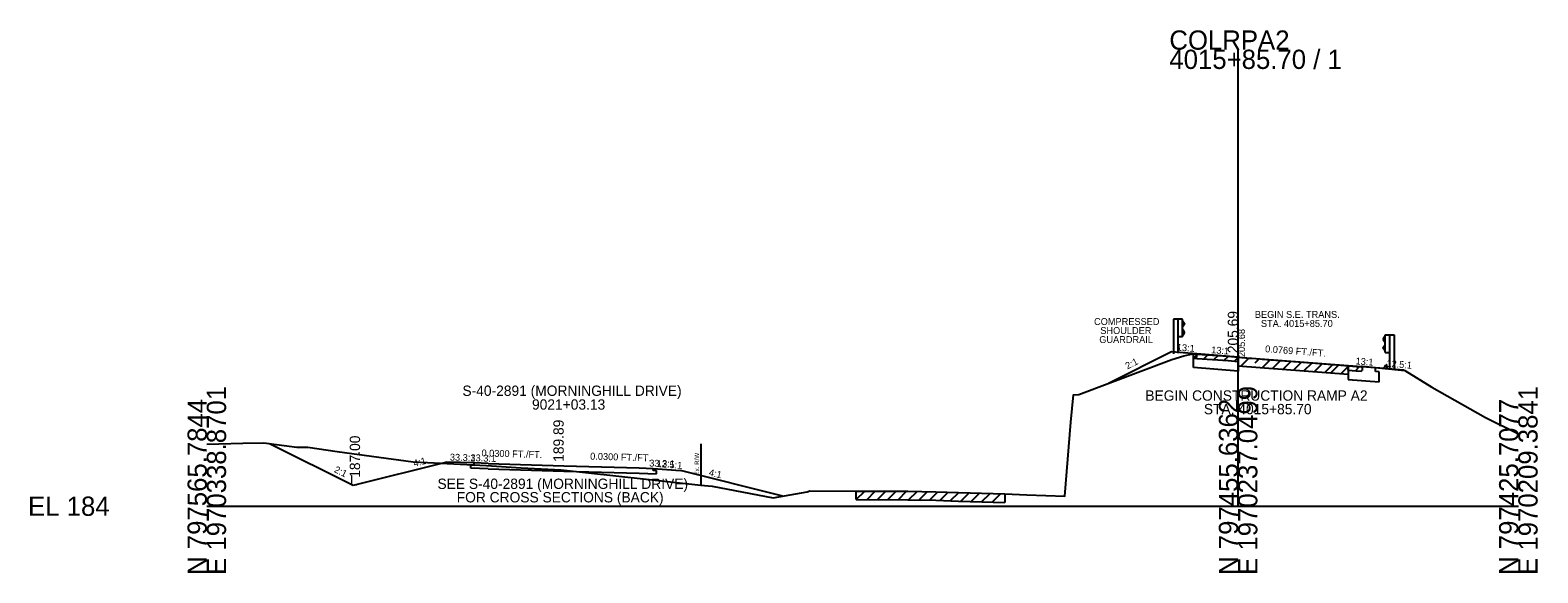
# Model space of a CAD drawing. Extents: x -26 to 1971083, y -10 to 798159.
# Drawn here: x -25.7 to 193.6, y -9.7 to 69.2 of the extents above; entities that cross this region are included whole.
import ezdxf

# ---------------------------------------------------------------- set-up
doc = ezdxf.new("R2010")
doc.units = 0
for name, color, linetype in [('RD_GPK_XS_Cell', 7, 'Continuous'), ('RD_XS_Base', 7, 'Continuous'), ('RD_XS_CurbTop', 7, 'Continuous'), ('RD_XS_EarthShd', 7, 'Continuous'), ('RD_XS_ExGround', 7, 'Continuous'), ('RD_XS_ExPaveRet', 7, 'Continuous'), ('RD_XS_ExRW', 7, 'Continuous'), ('RD_XS_GR', 7, 'Continuous'), ('RD_XS_Misc_Line', 7, 'Continuous'), ('RD_XS_Pave', 7, 'Continuous'), ('RD_XS_PaveOvlay', 7, 'Continuous'), ('RD_XS_PaveShd', 7, 'Continuous'), ('RD_XS_TieSlope', 7, 'Continuous'), ('RD_XS_TX_Elev_EX', 7, 'Continuous'), ('RD_XS_TX_Elev_PR', 7, 'Continuous'), ('RD_XS_TX_Misc', 7, 'Continuous'), ('RD_XS_TX_MkPT', 7, 'Continuous'), ('RD_XS_TX_Notes', 7, 'Continuous'), ('RD_XS_TX_Profile', 7, 'Continuous'), ('RD_XS_TX_ShdSlope', 7, 'Continuous'), ('RD_XS_TX_Slope', 7, 'Continuous'), ('RD_XS_TX_Station', 7, 'Continuous')]:
    doc.layers.add(name, color=color, linetype=linetype)

msp = doc.modelspace()

# ---------------------------------------------------------------- linework, layer by layer
at = {"layer": 'RD_GPK_XS_Cell'}
for p, q in [((150, 0), (150, 66.38)), ((0, 0), (150, 0)), ((150, 0), (190.76, 0))]:
    msp.add_line(p, q, dxfattribs=at)
at = {"layer": 'RD_XS_Base'}
for p, q in [((144, 21.6), (144, 22.16)), ((143.5, 21.63), (144, 21.6)), ((143.5, 20.15), (143.5, 21.63)), ((150, 19.65), (143.5, 20.15)), ((170, 19.6), (170, 20.16)), ((166, 18.42), (170.5, 18.08)), ((170.5, 19.56), (170, 19.6)), ((170.5, 18.08), (170.5, 19.56)), ((38.41, 5.99), (38.91, 5.98)), ((38.41, 5.51), (38.41, 5.99)), ((40.91, 5.44), (38.41, 5.51)), ((38.91, 5.98), (38.91, 6.28)), ((40.91, 5.44), (51.91, 5.11)), ((51.91, 5.11), (62.91, 4.78)), ((62.91, 4.78), (65.41, 4.7)), ((64.91, 5.2), (64.91, 5.5)), ((65.41, 5.18), (64.91, 5.2)), ((65.41, 4.7), (65.41, 5.18))]:
    msp.add_line(p, q, dxfattribs=at)
at = {"layer": 'RD_XS_CurbTop'}
for p, q in [((171.23, 20.06), (171.47, 20.51)), ((171.23, 20.06), (171.69, 20.02)), ((171.69, 20.02), (171.63, 20.46))]:
    msp.add_line(p, q, dxfattribs=at)
msp.add_ellipse((171.55, 20.43), major_axis=(0, -0.131), ratio=0.686, start_param=1.762783, end_param=4.036677, dxfattribs=at)
at = {"layer": 'RD_XS_EarthShd'}
for p, q in [((144, 22.16), (142.06, 22.31)), ((170, 20.16), (171.23, 20.06)), ((38.91, 6.28), (34.91, 6.4)), ((64.91, 5.5), (68.92, 5.18))]:
    msp.add_line(p, q, dxfattribs=at)
at = {"layer": 'RD_XS_ExGround'}
msp.add_lwpolyline([(0, 9.01), (5.25, 9.16), (8.3, 9.2), (13.11, 8.59), (14.69, 8.56), (18.98, 7.95), (30.02, 6.45), (32.11, 6.34), (40.68, 5.92), (45.71, 5.6), (51.53, 5.28), (71.86, 3.08), (72.94, 2.98), (73.48, 2.91), (82.4, 1.2), (87.3, 2.11), (87.7, 2.22), (94.46, 2.2), (101.96, 2.16), (106.04, 2.11), (109.32, 2), (116.09, 1.79), (119.29, 1.66), (124.78, 1.45), (125.69, 12.23), (126.08, 16.21), (126.84, 16.25), (140.37, 21.31), (142.12, 21.88), (143, 22.04), (143.49, 22.13), (144, 22.09), (148.57, 21.81), (150, 21.68), (151.62, 21.52), (152, 21.5), (164.93, 20.53), (167.17, 20.3), (167.9, 20.25), (168.05, 20.37), (174.23, 19.75), (178.16, 17.29), (185.99, 12.92), (190.76, 10.54)], dxfattribs=at)
at = {"layer": 'RD_XS_ExPaveRet'}
for p, q in [((143.49, 21.5), (143.49, 22.13)), ((143.49, 21.5), (144, 21.46)), ((144, 21.46), (148.57, 21.19)), ((148.57, 21.19), (150, 21.05)), ((150, 20.4), (150, 21.68)), ((150, 21.68), (150, 21.05)), ((150, 20.4), (166, 19.2)), ((166, 20.42), (166, 19.17)), ((166, 19.8), (166, 20.42)), ((166, 19.8), (167.17, 19.68)), ((167.9, 19.62), (168.05, 19.75)), ((168.05, 20.37), (168.05, 19.75)), ((167.17, 19.68), (167.9, 19.62)), ((94.46, 0.95), (94.46, 2.2)), ((94.46, 0.95), (101.96, 0.91)), ((101.96, 0.91), (106.04, 0.86)), ((106.04, 0.86), (109.32, 0.75)), ((109.32, 0.75), (116.09, 0.54)), ((116.09, 1.79), (116.09, 0.54))]:
    msp.add_line(p, q, dxfattribs=at)
at = {"layer": 'RD_XS_ExRW'}
msp.add_line((71.86, 9.08), (71.86, 3.08), dxfattribs=at)
at = {"layer": 'RD_XS_GR'}
for p, q in [((141.24, 27.18), (140.58, 27.18)), ((140.58, 27.18), (140.58, 22.13)), ((141.91, 27.18), (141.24, 27.18)), ((141.24, 27.18), (141.24, 22.24)), ((141.91, 24.61), (141.91, 27.18)), ((141.91, 27.02), (142.18, 26.58)), ((142.18, 26.47), (141.91, 26.03)), ((142.18, 26.58), (142.18, 26.47)), ((141.91, 24.61), (141.24, 24.61)), ((142.18, 25.32), (141.91, 25.76)), ((141.91, 24.77), (142.18, 25.21)), ((142.18, 25.21), (142.18, 25.32)), ((171.37, 24.77), (171.1, 24.33)), ((171.1, 24.33), (171.1, 24.22)), ((171.1, 24.22), (171.37, 23.78)), ((171.37, 24.93), (172.04, 24.93)), ((171.37, 22.37), (171.37, 24.93)), ((172.04, 24.93), (172.7, 24.93)), ((172.04, 24.93), (172.04, 19.99)), ((172.7, 24.93), (172.7, 19.88)), ((171.1, 23.08), (171.37, 23.52)), ((171.1, 22.97), (171.1, 23.08)), ((171.37, 22.53), (171.1, 22.97)), ((171.37, 22.37), (172.04, 22.37))]:
    msp.add_line(p, q, dxfattribs=at)
at = {"layer": 'RD_XS_Misc_Line'}
for p, q in [((143.49, 21.5), (144.07, 22.09)), ((144.99, 21.4), (145.58, 21.99)), ((146.49, 21.31), (147.08, 21.9)), ((147.99, 21.22), (148.58, 21.81)), ((149.49, 21.1), (150.06, 21.67)), ((150.4, 20.37), (151.56, 21.53)), ((152.49, 20.83), (153.07, 21.42)), ((153.49, 20.13), (154.67, 21.3)), ((155.01, 20.02), (156.19, 21.18)), ((156.53, 19.91), (157.71, 21.07)), ((158.05, 19.79), (159.23, 20.95)), ((159.57, 19.68), (160.75, 20.84)), ((161.09, 19.57), (162.27, 20.73)), ((162.61, 19.45), (163.79, 20.61)), ((163.47, 19.39), (164.64, 20.55)), ((164.99, 19.27), (166.12, 20.41)), ((167.06, 19.69), (167.63, 20.27)), ((94.46, 0.95), (95.71, 2.19)), ((95.98, 0.94), (97.23, 2.18)), ((97.5, 0.93), (98.75, 2.17)), ((99.02, 0.92), (100.27, 2.17)), ((100.54, 0.91), (101.79, 2.16)), ((102.06, 0.9), (103.31, 2.14)), ((103.58, 0.89), (104.83, 2.13)), ((105.1, 0.87), (106.34, 2.1)), ((106.62, 0.84), (107.84, 2.05)), ((108.14, 0.79), (109.36, 2)), ((109.66, 0.74), (110.88, 1.95)), ((111.18, 0.69), (112.4, 1.9)), ((112.7, 0.64), (113.92, 1.86)), ((114.22, 0.6), (115.44, 1.81))]:
    msp.add_line(p, q, dxfattribs=at)
at = {"layer": 'RD_XS_Pave'}
for p, q in [((150, 21.69), (166, 20.46)), ((40.91, 6.22), (51.91, 5.89)), ((51.91, 5.89), (62.91, 5.56))]:
    msp.add_line(p, q, dxfattribs=at)
at = {"layer": 'RD_XS_PaveOvlay'}
for p, q in [((150, 21.68), (150, 19.65)), ((150, 20.63), (150, 19.68)), ((153.49, 21.38), (164.05, 20.59)), ((164.05, 20.59), (166, 20.42)), ((166, 20.42), (166, 18.42))]:
    msp.add_line(p, q, dxfattribs=at)
at = {"layer": 'RD_XS_PaveShd'}
for p, q in [((150, 21.69), (144, 22.16)), ((166, 20.46), (170, 20.16)), ((40.91, 6.22), (38.91, 6.28)), ((62.91, 5.56), (64.91, 5.5))]:
    msp.add_line(p, q, dxfattribs=at)
at = {"layer": 'RD_XS_TieSlope'}
for p, q in [((140.31, 22.44), (131.14, 17.86)), ((142.06, 22.31), (140.31, 22.44)), ((171.23, 20.06), (174.06, 19.83)), ((174.06, 19.83), (174.23, 19.75)), ((21.31, 3), (9.13, 9.09)), ((34.91, 6.4), (21.31, 3)), ((83.8, 1.46), (68.92, 5.18))]:
    msp.add_line(p, q, dxfattribs=at)

# ---------------------------------------------------------------- texts
at = {"layer": 'RD_GPK_XS_Cell'}
for s, p in [('COLRPA2', (140, 66.38)), ('4015+85.70 / 1', (140, 63.58)), ('EL 184', (-26, -1.4))]:
    msp.add_text(s, height=2.8, dxfattribs=at).set_placement(p)
for s, p in [('N 797565.7844', (0, -10)), ('E 1970338.8701', (2.8, -10)), ('N 797455.6362', (150, -10)), ('E 1970237.0499', (152.8, -10)), ('N 797425.7077', (190.76, -10)), ('E 1970209.3841', (193.56, -10))]:
    msp.add_text(s, height=2.8, rotation=90, dxfattribs=at).set_placement(p)
at = {"layer": 'RD_XS_ExRW'}
msp.add_text('Ex. R/W ', height=0.65, rotation=90, dxfattribs=at).set_placement((71.61, 4.47))
at = {"layer": 'RD_XS_TX_Elev_EX'}
msp.add_text('205.68', height=1, rotation=90, dxfattribs=at).set_placement((151, 21.68))
at = {"layer": 'RD_XS_TX_Elev_PR'}
for s, p in [(' 205.69', (150, 21.69)), (' 189.89', (51.91, 5.89))]:
    msp.add_text(s, height=1.5, rotation=90, dxfattribs=at).set_placement(p)
at = {"layer": 'RD_XS_TX_Misc'}
msp.add_text('187.00', height=1.5, rotation=90, dxfattribs=at).set_placement((22.29, 4.13))
at = {"layer": 'RD_XS_TX_MkPT'}
msp.add_text('L', height=1.5, dxfattribs=at).set_placement((20.81, 3))
at = {"layer": 'RD_XS_TX_Notes'}
for s, p in [('COMPRESSED', (129.05, 26.35)), ('BEGIN S.E. TRANS.', (152.44, 27.38)), ('STA. 4015+85.70', (153.32, 26.07)), ('GUARDRAIL', (129.81, 23.73)), ('SHOULDER', (129.96, 25.04))]:
    msp.add_text(s, height=1, rotation=360, dxfattribs=at).set_placement(p)
for s, p in [('BEGIN CONSTRUCTION RAMP A2', (136.51, 15.34)), ('STA. 4015+85.70', (145.02, 13.37)), ('SEE S-40-2891 (MORNINGHILL DRIVE)', (33.55, 2.51)), ('FOR CROSS SECTIONS (BACK)', (36.35, 0.55))]:
    msp.add_text(s, height=1.5, dxfattribs=at).set_placement(p)
at = {"layer": 'RD_XS_TX_Profile'}
for p in [(38.34, 6.55), (64.34, 5.77)]:
    msp.add_text('33.3:1', height=1, rotation=358.2815, dxfattribs=at).set_placement(p)
at = {"layer": 'RD_XS_TX_ShdSlope'}
for s, rotation, p in [('13:1', 355.6026, (141.06, 22.63)), ('12.5:1', 355.4261, (171.54, 20.28)), ('33.3:1', 358.2815, (35.34, 6.64)), ('12.5:1', 355.4323, (65.41, 5.71))]:
    msp.add_text(s, height=1, rotation=rotation, dxfattribs=at).set_placement(p)
at = {"layer": 'RD_XS_TX_Slope'}
for s, rotation, p in [('13:1', 355.6026, (146.06, 22.25)), ('0.0769 FT./FT.', 355.6026, (153.9, 22.4)), ('2:1', 26.5651, (133.9, 19.87)), ('13:1', 355.6026, (167.06, 20.63)), ('4:1', 14.0362, (30.17, 5.73)), ('0.0300 FT./FT.', 358.2815, (39.94, 7.25)), ('0.0300 FT./FT.', 358.2815, (55.75, 6.78)), ('2:1', 333.435, (18.43, 5)), ('4:1', 346.9381, (72.96, 4.46))]:
    msp.add_text(s, height=1, rotation=rotation, dxfattribs=at).set_placement(p)
at = {"layer": 'RD_XS_TX_Station'}
for s, p in [('S-40-2891 (MORNINGHILL DRIVE)', (37.18, 16.04)), ('9021+03.13', (47.3, 14.04))]:
    msp.add_text(s, height=1.5, dxfattribs=at).set_placement(p)

doc.saveas('drawing.dxf')
